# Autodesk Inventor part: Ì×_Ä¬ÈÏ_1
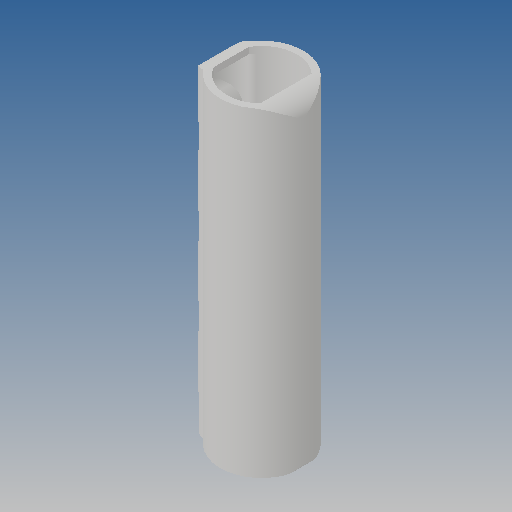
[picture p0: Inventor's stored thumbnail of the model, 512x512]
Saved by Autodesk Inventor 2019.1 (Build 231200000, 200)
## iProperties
Created: 2012-10
Part Number: Ì×_Ä¬ÈÏ_1
Material: Ogólny
Document SubType Name: Modeling
Designer: CADENGINEERING4
Density: 1 g/cm^3
Appearance: Domyślna
Author: CADENGINEERING4
Revision Number: ÈÎºÎ
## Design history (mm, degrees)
feature "NONE"
node "Bryła1"
